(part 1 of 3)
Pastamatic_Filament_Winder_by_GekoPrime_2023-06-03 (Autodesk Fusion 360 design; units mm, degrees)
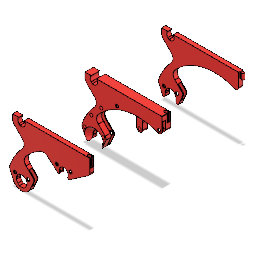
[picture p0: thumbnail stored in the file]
description: Spur Gear; Module: 2.0; Num Teeth: 20; Pressure Angle: 20.0; Backlash: 0.00 mm
description: Spur Gear; Module: 2.0; Num Teeth: 40; Pressure Angle: 20.0; Backlash: 0.00 mm
description: Spur Gear; Module: 2.0; Num Teeth: 10; Pressure Angle: 20.0; Backlash: 0.00 mm
description: Spur Gear; Module: 2.0; Num Teeth: 50; Pressure Angle: 20.0; Backlash: 0.00 mm
description: Spur Gear; Module: 2.0; Num Teeth: 30; Pressure Angle: 20.0; Backlash: 0.00 mm
parameter "bearing_od" = 22
parameter "bearing_id" = 8
parameter "bearing_z" = 7
parameter "spool_id_min" = 50
parameter "spool_id_max" = 60
parameter "spool_od_max" = 250
parameter "spool_z_max" = 120
parameter "ptfe_od" = 4
parameter "drive_span" = 6.65 (= "clearance_loose + 1 / 4 * 1 in")
parameter "overhang_angle" = 45
parameter "spool_z_min" = 50
parameter "spur_gear_z" = 7 (= "bearing_z")
parameter "spur_gear_diameter_medium" = 40
parameter "axle_od" = 26 (= "bearing_od + 2 * wall_thickness")
parameter "leadscrew_pitch" = 30 (= "spool_inner_z_bambu / leadscrew_turns")
parameter "leadscrew_tooth_height" = 3.3333 (= "leadscrew_od / 6")
parameter "clearance_loose" = 0.3
parameter "screw_od" = 22 (= "axle_od - 2 * wall_thickness")
parameter "screw_pitch" = 22 (= "screw_od")
parameter "screw_id" = 18 (= "screw_od - 2 * wall_thickness")
parameter "wall_thickness" = 2
parameter "washer_z" = 0.3 (= "clearance_loose")
parameter "leadscrew_angle" = 64.477 (= "atan(PI * leadscrew_od / leadscrew_pitch)")
parameter "washer_radial_thichness" = 1
parameter "internal_cavity_thickness" = 1
parameter "clearance_tight" = 0.01
parameter "buildplate_limit" = 240
parameter "spur_gear_diameter_small" = 20
parameter "stack_unit" = 11.6 (= "bearing_z + 2 * washer_z + 2 * wall_thickness")
parameter "fillet_radius" = 2 (= "wall_thickness")
parameter "spur_gear_diameter_large" = 100
parameter "ground_clearance" = 20
parameter "drive_depth" = 25.4
parameter "spool_id_bambu" = 54
parameter "spool_od_bambu" = 200
parameter "spool_inner_z_bambu" = 60
parameter "leadscrew_od" = 20
parameter "crossbar_od" = 20 (= "ground_clearance")
parameter "leadscrew_length" = 200
parameter "leadscrew_center_position" = 68.928
parameter "spur_gear_clearance" = 4
parameter "motor_mounting_circle" = 31
parameter "washer_taper" = -45
parameter "spool_interface_z_bambu" = 62
parameter "spool_od_min" = 200
sketch "Sketch1" plane through (0, 0, 0) normal (0, 0, 1) x axis (1, 0, 0)
  circle C1 centre (0, 0) radius 7.5492
extrude "Extrude1" new body sketch "Sketch1" along normal blind 7 bodies "spur_gear_10t_7mm"
sketch "Sketch2" plane through (0, 0, 0) normal (0, 0, 1) x axis (1, 0, 0)
  curve K1 (11.9856, -0.5875) -> (9.2583, -1.6082)
  curve K2 (11.9856, 0.5875) -> (9.2583, 1.6082)
  line L1 (9.2583, -1.6082) -> (7.428, -1.292)
  line L2 (9.2583, 1.6082) -> (7.428, 1.292)
  line L3 (7.428, 1.292) -> (7.428, -1.292)
  arc A1 centre (0, 0) radius 12 clockwise from (11.9856, 0.5875) to (11.9856, -0.5875)
extrude "Extrude2" add sketch "Sketch2" along normal blind 7
fillet "Fillet1" radius 1
circular_pattern "C-Pattern1" countU 10 TotalAngle 360
sketch "Sketch3" plane through (0, 0, 0) normal (0, 0, 1) x axis (1, 0, 0)
  circle C1 centre (0, 0) radius 10
sketch "Sketch1" plane through (0, 0, 0) normal (0, 0, 1) x axis (1, 0, 0)
  circle C1 centre (0, 0) radius 17.5492
  circle C2 centre (0, 0) radius 11
extrude "Extrude1" new body sketch "Sketch1" along normal blind 7 bodies "idler"
sketch "Sketch2" plane through (0, 0, 0) normal (0, 0, 1) x axis (1, 0, 0)
  curve K1 (21.989, -0.6948) -> (18.7119, -1.7536)
  curve K2 (21.989, 0.6948) -> (18.7119, 1.7536)
  line L1 (18.7119, -1.7536) -> (17.4627, -1.6375)
  line L2 (18.7119, 1.7536) -> (17.4627, 1.6375)
  line L3 (17.4627, 1.6375) -> (17.4627, -1.6375)
  arc A1 centre (0, 0) radius 22 clockwise from (21.989, 0.6948) to (21.989, -0.6948)
extrude "Extrude2" add sketch "Sketch2" along normal blind 7
fillet "Fillet1" radius 1
circular_pattern "C-Pattern1" countU 20 TotalAngle 360
sketch "Sketch3" plane through (0, 0, 0) normal (0, 0, 1) x axis (1, 0, 0)
  circle C1 centre (0, 0) radius 20
sketch "Sketch4" plane through (0, 0, 0) normal (1, 0, 0) x axis (0, 0, -1)
  line L1 (0, -22) -> (0, -21.989)
  line L2 (-7, -22) -> (-7, -21.989)
  line L3 (0, 21.989) -> (0, 22)
  line L4 (-7, 21.989) -> (-7, 22)
  line L5 (-7, -22) -> (0, -22)
  line L6 (-7, 22) -> (-7, -21.989)
  line L7 (0, -21.989) -> (0, 21.989)
  line L8 (-7, 19.652) -> (-4.663, 21.989)
  line L9 (0, 19.652) -> (-2.326, 22)
  line L10 (0, 0) -> (-7, 0.0055)
  line L11 (-3.5, 22) -> (-3.5, 19.652)
  line L12 (0, 19.652) -> (-3.5, 19.652)
  line L13 (-7, 19.652) -> (-3.5, 19.652)
  line L14 (-2.326, 22) -> (-4.663, 21.989)
  line L15 (0, 22) -> (-2.326, 22)
  line L16 (-7, 21.989) -> (-4.663, 21.989)
  point P4 (-7, -21.989)
  point P10 (-7, -21.989)
  point P9 (-7, 22)
  point P11 (-7, 22)
  point P6 (0, 21.989)
  point P12 (0, 21.989)
  point P2 (0, -21.989)
  point P13 (0, -21.989)
  point P15 (-7, 19.652)
  point P17 (0, 19.652)
  point P18 (-7, 0.0055)
  point P1 (0, 0)
  point P19 (0, 0)
  point P8 (0, 22)
  point P22 (0, 22)
  point P7 (-7, 21.989)
  point P23 (-7, 21.989)
  coincident P4 P10
  coincident P9 P11
  coincident P6 P12
  coincident P2 P13
  coincident L6 P15
  coincident L7 P17
  midpoint L6 P18
  coincident P1 P19
  equal L8 L9
  perpendicular L7 L12
  perpendicular L6 L13
  perpendicular L11 L12
  coincident P8 P22
  coincident P7 P23
  perpendicular L7 L15
  perpendicular L6 L16
  equal L12 L13
  equal L14 L16
  dimension "d1268" angle L6 L8 = 45
revolve "Revolve1" sketch "Sketch4" AlongAngle 360
chamfer "Chamfer1" distance 1
sketch "Sketch1" plane through (0, 0, 0) normal (0, 0, 1) x axis (1, 0, 0)
  circle C1 centre (0, 0) radius 37.5492
  circle C2 centre (0, 0) radius 11
extrude "Extrude1" new body sketch "Sketch1" along normal blind 7 bodies "spur_gear_40t_7mm"
sketch "Sketch2" plane through (0, 0, 0) normal (0, 0, 1) x axis (1, 0, 0)
  curve K1 (41.9931, -0.7606) -> (37.5326, -2.0353)
  curve K2 (41.9931, 0.7606) -> (37.5326, 2.0353)
  line L1 (37.5326, -2.0353) -> (37.4841, -2.0332)
  line L2 (37.5326, 2.0353) -> (37.4841, 2.0332)
  line L3 (37.4841, 2.0332) -> (37.4841, -2.0332)
  arc A1 centre (0, 0) radius 42 clockwise from (41.9931, 0.7606) to (41.9931, -0.7606)
extrude "Extrude2" add sketch "Sketch2" along normal blind 7
fillet "Fillet1" radius 1
circular_pattern "C-Pattern1" countU 40 TotalAngle 360
sketch "Sketch3" plane through (0, 0, 0) normal (0, 0, 1) x axis (1, 0, 0)
  circle C1 centre (0, 0) radius 40
sketch "Sketch1" plane through (0, 0, 0) normal (0, 0, 1) x axis (1, 0, 0)
  circle C1 centre (0, 0) radius 47.5492
extrude "Extrude1" new body sketch "Sketch1" along normal blind 7 bodies "spur_gear_50t_7mm"
sketch "Sketch2" plane through (0, 0, 0) normal (0, 0, 1) x axis (1, 0, 0)
  curve K1 (51.9942, -0.7754) -> (46.9342, -2.1756)
  curve K2 (51.9942, 0.7754) -> (46.9342, 2.1756)
  line L1 (46.9342, -2.1756) -> (46.9342, 2.1756)
  arc A1 centre (0, 0) radius 52 clockwise from (51.9942, 0.7754) to (51.9942, -0.7754)
extrude "Extrude2" add sketch "Sketch2" along normal blind 7
fillet "Fillet1" radius 1
circular_pattern "C-Pattern1" countU 50 TotalAngle 360
sketch "Sketch3" plane through (0, 0, 0) normal (0, 0, 1) x axis (1, 0, 0)
  circle C1 centre (0, 0) radius 50
sketch "Sketch5" plane through (0, 0, 0) normal (1, 0, 0) x axis (0, 0, -1)
  line L1 (-7, 51.9403) -> (0, 51.9403)
  line L2 (0, 49.607) -> (-3.5, 53.107)
  line L3 (0, 51.9403) -> (0, 49.607)
  line L4 (-7, 49.607) -> (-7, 51.9403)
  line L5 (-3.5, 53.107) -> (-7, 49.607)
  line L6 (-7, 53.107) -> (-7, 51.9403)
  line L7 (0, 53.107) -> (-7, 53.107)
  line L8 (0, 51.9403) -> (0, 53.107)
  point P2 (0, 51.9403)
  point P6 (0, 51.9403)
  point P3 (-7, 51.9403)
  point P7 (-7, 51.9403)
  point P10 (-7, 51.9403)
  point P13 (0, 51.9403)
  point P14 (-4.6667, 51.9403)
  point P15 (-2.3333, 51.9403)
  point P9 (-3.5, 53.107)
  point P4 (-3.5, 53.107)
  coincident P2 P6
  coincident P3 P7
  perpendicular L1 L4
  perpendicular L1 L3
  equal L2 L5
  equal L3 L4
  coincident P3 P10
  perpendicular L1 L6
  coincident P2 P13
  perpendicular L1 L8
  coincident L5 P14
  coincident L1 P14
  coincident L1 P15
  coincident L2 P15
  perpendicular L6 L7
  coincident P9 L7
  coincident P4 L7
  coincident P4 P9
  dimension "d1416" angle L4 L5 = 45
  dimension "d1419" distance P14 P15 = 2.3333 (= "bearing_z / 3")
revolve "Revolve1" sketch "Sketch5" AlongAngle 360
sketch "Sketch1" plane through (0, 0, 0) normal (0, 0, 1) x axis (1, 0, 0)
  line L1 (1.6583, -2.5) -> (-1.6583, -2.5)
  line L2 (4, 3) -> (-5, 3)
  circle C1 centre (0, 0) radius 7.5492
  circle C2 centre (0, 0) radius 3
  point P4 (-1.6583, -2.5)
  point P5 (1.6583, -2.5)
  concentric C1 C2
  coincident C2 P4
  coincident C2 P5
  horizontal L1
  horizontal L2
  tangent C2 L2
  dimension "d1565" distance L1 L2 = 5.5
  dimension "d1566" diameter C2 = 6
extrude "Extrude1" new body sketch "Sketch1" profile of C1 C2 L1 along normal blind 14 named "d988_1" bodies "spur_gear_10t_14mm_6mmD"
sketch "Sketch2" plane through (0, 0, 0) normal (0, 0, 1) x axis (1, 0, 0)
  curve K1 (11.9856, -0.5875) -> (9.2583, -1.6082)
  curve K2 (11.9856, 0.5875) -> (9.2583, 1.6082)
  line L1 (9.2583, -1.6082) -> (7.428, -1.292)
  line L2 (9.2583, 1.6082) -> (7.428, 1.292)
  line L3 (7.428, 1.292) -> (7.428, -1.292)
  arc A1 centre (0, 0) radius 12 clockwise from (11.9856, 0.5875) to (11.9856, -0.5875)
extrude "Extrude2" add sketch "Sketch2" along normal blind 14 named "d990_1"
fillet "Fillet1" radius 1 named "d993_1"
circular_pattern "C-Pattern1" countU 10 named "d994_1" TotalAngle 360 named "d995_1"
sketch "Sketch3" plane through (0, 0, 0) normal (0, 0, 1) x axis (1, 0, 0)
  circle C1 centre (0, 0) radius 10
sketch "Sketch4" plane through (0, 0, 0) normal (0, 1, 0) x axis (1, 0, 0)
  line L1 (0, 0) -> (0, -14)
  line L2 (9.6667, 0) -> (0, 0)
  line L3 (12, -2.3333) -> (9.6667, 0)
  line L4 (12, -11.6667) -> (12, -2.3333)
  line L5 (9.6667, -14) -> (12, -11.6667)
  line L6 (0, -14) -> (9.6667, -14)
  line L7 (0, -7) -> (12, -7)
  point P1 (0, 0)
  point P3 (0, 0)
  point P8 (12, -7)
  point P9 (0, -7)
  point P2 (0, -14)
  point P5 (12, -2.3333)
  point P6 (12, -11.6667)
  coincident P1 P3
  vertical L1
  perpendicular L1 L2
  perpendicular L2 L4
  perpendicular L1 L6
  equal L3 L5
  midpoint L4 P8
  midpoint L1 P9
  perpendicular L4 L7
  dimension "d1567" distance P2 P3 = 14
  dimension "d1568" distance L1 L4 = 12 (= "spur_gear_diameter_small / 2 + spur_gear_clearance / 2")
  dimension "d1569" angle L5 L6 = 45
  dimension "d1570" distance P5 P6 = 9.3333 (= "7 mm + ( 7 / 3 ) * 1 mm")
revolve "Revolve1" sketch "Sketch4" AlongAngle 360
sketch "Sketch1" plane through (0, 0, 0) normal (0, 0, 1) x axis (1, 0, 0)
  circle C1 centre (0, 0) radius 27.5492
extrude "Extrude1" new body sketch "Sketch1" along normal blind 7 bodies "spur_gear_30t_7mm"
sketch "Sketch2" plane through (0, 0, 0) normal (0, 0, 1) x axis (1, 0, 0)
  curve K1 (31.9915, -0.7373) -> (28.127, -1.8948)
  curve K2 (31.9915, 0.7373) -> (28.127, 1.8948)
  line L1 (28.127, -1.8948) -> (27.4769, -1.8517)
  line L2 (28.127, 1.8948) -> (27.4769, 1.8517)
  line L3 (27.4769, 1.8517) -> (27.4769, -1.8517)
  arc A1 centre (0, 0) radius 32 clockwise from (31.9915, 0.7373) to (31.9915, -0.7373)
extrude "Extrude2" add sketch "Sketch2" along normal blind 7
fillet "Fillet1" radius 1
circular_pattern "C-Pattern1" countU 30 TotalAngle 360
sketch "Sketch3" plane through (0, 0, 0) normal (0, 0, 1) x axis (1, 0, 0)
  circle C1 centre (0, 0) radius 30
copy_paste_bodies "CopyPasteBodies3"
copy_paste_bodies "CopyPasteBodies2"
align "Align1"
move "Move1" TranslateX 0 TranslateY 0 TranslateZ -4 (= "-2 * wall_thickness")
sketch "Sketch1" plane through (0, 0, 7) normal (0, 0, 1) x axis (1, 0, 0)
  curve K1 (27.4076, 2.7893) -> (28.3353, 1.8928)
  curve K2 (31.9915, 0.7373) -> (28.3353, 1.8928)
  curve K3 (28.3353, -1.8928) -> (31.9915, -0.7373)
  curve K4 (28.3353, -1.8928) -> (27.4076, -2.7893)
  curve K5 (27.3886, -2.97) -> (28.1096, -4.0398)
  curve K6 (31.4457, -5.9302) -> (28.1096, -4.0398)
  curve K7 (27.3226, -7.7427) -> (31.1391, -7.3726)
  curve K8 (27.3226, -7.7427) -> (26.2288, -8.4267)
  curve K9 (26.1726, -8.5996) -> (26.6554, -9.7959)
  curve K10 (29.5256, -12.3385) -> (26.6554, -9.7959)
  curve K11 (25.1157, -13.2541) -> (28.9258, -13.6857)
  curve K12 (25.1157, -13.2541) -> (23.9036, -13.6958)
  curve K13 (23.8127, -13.8532) -> (24.0363, -15.1238)
  curve K14 (26.3151, -18.2076) -> (24.0363, -15.1238)
  curve K15 (21.8112, -18.1864) -> (25.4483, -19.4007)
  curve K16 (21.8112, -18.1864) -> (20.5337, -18.3664)
  curve K17 (20.4121, -18.5015) -> (20.3666, -19.7907)
  curve K18 (21.9544, -23.2809) -> (20.3666, -19.7907)
  curve K19 (17.5534, -22.3237) -> (20.8585, -24.2677)
  curve K20 (17.5534, -22.3237) -> (16.2665, -22.2342)
  curve K21 (16.1194, -22.3411) -> (15.8068, -23.5927)
  curve K22 (16.6343, -27.3368) -> (15.8068, -23.5927)
  curve K23 (12.5284, -25.4855) -> (15.3572, -28.0741)
  curve K24 (12.5284, -25.4855) -> (11.2882, -25.1303)
  curve K25 (11.1222, -25.2043) -> (10.5562, -26.3636)
  curve K26 (10.5872, -30.1979) -> (10.5562, -26.3636)
  curve K27 (6.9559, -27.5334) -> (9.1847, -30.6536)
  curve K28 (6.9559, -27.5334) -> (5.8167, -26.9281)
  curve K29 (5.6389, -26.9659) -> (4.8443, -27.9822)
  curve K30 (4.0773, -31.7392) -> (4.8443, -27.9822)
  curve K31 (1.0794, -28.3779) -> (2.6107, -31.8933)
  curve K32 (1.0794, -28.3779) -> (0.0909, -27.5491)
  curve K33 (-0.0909, -27.5491) -> (-1.0794, -28.3779)
  curve K34 (-2.6107, -31.8933) -> (-1.0794, -28.3779)
  curve K35 (-4.8443, -27.9822) -> (-4.0773, -31.7392)
  curve K36 (-4.8443, -27.9822) -> (-5.6389, -26.9659)
  curve K37 (-5.8167, -26.9281) -> (-6.9559, -27.5334)
  curve K38 (-9.1847, -30.6536) -> (-6.9559, -27.5334)
  curve K39 (-10.5562, -26.3636) -> (-10.5872, -30.1979)
  curve K40 (-10.5562, -26.3636) -> (-11.1222, -25.2043)
  curve K41 (-11.2882, -25.1303) -> (-12.5284, -25.4855)
  curve K42 (-15.3572, -28.0741) -> (-12.5284, -25.4855)
  curve K43 (-15.8068, -23.5927) -> (-16.6343, -27.3368)
  curve K44 (-15.8068, -23.5927) -> (-16.1194, -22.3411)
  curve K45 (-16.2665, -22.2342) -> (-17.5534, -22.3237)
  curve K46 (-20.8585, -24.2677) -> (-17.5534, -22.3237)
  curve K47 (-20.3666, -19.7907) -> (-21.9544, -23.2809)
  curve K48 (-20.3666, -19.7907) -> (-20.4121, -18.5015)
  curve K49 (-20.5337, -18.3664) -> (-21.8112, -18.1864)
  curve K50 (-25.4483, -19.4007) -> (-21.8112, -18.1864)
  curve K51 (-24.0363, -15.1238) -> (-26.3151, -18.2076)
  curve K52 (-24.0363, -15.1238) -> (-23.8127, -13.8532)
  curve K53 (-23.9036, -13.6958) -> (-25.1157, -13.2541)
  curve K54 (-28.9258, -13.6857) -> (-25.1157, -13.2541)
  curve K55 (-26.6554, -9.7959) -> (-29.5256, -12.3385)
  curve K56 (-26.6554, -9.7959) -> (-26.1726, -8.5996)
  curve K57 (-26.2288, -8.4267) -> (-27.3226, -7.7427)
  curve K58 (-31.1391, -7.3726) -> (-27.3226, -7.7427)
  curve K59 (-28.1096, -4.0398) -> (-31.4457, -5.9302)
  curve K60 (-28.1096, -4.0398) -> (-27.3886, -2.97)
  curve K61 (-27.4076, -2.7893) -> (-28.3353, -1.8928)
  curve K62 (-31.9915, -0.7373) -> (-28.3353, -1.8928)
  curve K63 (-28.3353, 1.8928) -> (-31.9915, 0.7373)
  curve K64 (-28.3353, 1.8928) -> (-27.4076, 2.7893)
  curve K65 (-27.3886, 2.97) -> (-28.1096, 4.0398)
  curve K66 (-31.4457, 5.9302) -> (-28.1096, 4.0398)
  curve K67 (-27.3226, 7.7427) -> (-31.1391, 7.3726)
  curve K68 (-27.3226, 7.7427) -> (-26.2288, 8.4267)
  curve K69 (-26.1726, 8.5996) -> (-26.6554, 9.7959)
  curve K70 (-29.5256, 12.3385) -> (-26.6554, 9.7959)
  curve K71 (-25.1157, 13.2541) -> (-28.9258, 13.6857)
  curve K72 (-25.1157, 13.2541) -> (-23.9036, 13.6958)
  curve K73 (-23.8127, 13.8532) -> (-24.0363, 15.1238)
  curve K74 (-26.3151, 18.2076) -> (-24.0363, 15.1238)
  curve K75 (-21.8112, 18.1864) -> (-25.4483, 19.4007)
  curve K76 (-21.8112, 18.1864) -> (-20.5337, 18.3664)
  curve K77 (-20.4121, 18.5015) -> (-20.3666, 19.7907)
  curve K78 (-21.9544, 23.2809) -> (-20.3666, 19.7907)
  curve K79 (-17.5534, 22.3237) -> (-20.8585, 24.2677)
  curve K80 (-17.5534, 22.3237) -> (-16.2665, 22.2342)
  curve K81 (-16.1194, 22.3411) -> (-15.8068, 23.5927)
  curve K82 (-16.6343, 27.3368) -> (-15.8068, 23.5927)
  curve K83 (-12.5284, 25.4855) -> (-15.3572, 28.0741)
  curve K84 (-12.5284, 25.4855) -> (-11.2882, 25.1303)
  curve K85 (-11.1222, 25.2043) -> (-10.5562, 26.3636)
  curve K86 (-10.5872, 30.1979) -> (-10.5562, 26.3636)
  curve K87 (-6.9559, 27.5334) -> (-9.1847, 30.6536)
  curve K88 (-6.9559, 27.5334) -> (-5.8167, 26.9281)
  curve K89 (-5.6389, 26.9659) -> (-4.8443, 27.9822)
  curve K90 (-4.0773, 31.7392) -> (-4.8443, 27.9822)
  curve K91 (-1.0794, 28.3779) -> (-2.6107, 31.8933)
  curve K92 (-1.0794, 28.3779) -> (-0.0909, 27.5491)
  curve K93 (0.0909, 27.5491) -> (1.0794, 28.3779)
  curve K94 (2.6107, 31.8933) -> (1.0794, 28.3779)
  curve K95 (4.8443, 27.9822) -> (4.0773, 31.7392)
  curve K96 (4.8443, 27.9822) -> (5.6389, 26.9659)
  curve K97 (5.8167, 26.9281) -> (6.9559, 27.5334)
  curve K98 (9.1847, 30.6536) -> (6.9559, 27.5334)
  curve K99 (10.5562, 26.3636) -> (10.5872, 30.1979)
  curve K100 (10.5562, 26.3636) -> (11.1222, 25.2043)
  curve K101 (11.2882, 25.1303) -> (12.5284, 25.4855)
  curve K102 (15.3572, 28.0741) -> (12.5284, 25.4855)
  curve K103 (15.8068, 23.5927) -> (16.6343, 27.3368)
  curve K104 (15.8068, 23.5927) -> (16.1194, 22.3411)
  curve K105 (16.2665, 22.2342) -> (17.5534, 22.3237)
  curve K106 (20.8585, 24.2677) -> (17.5534, 22.3237)
  curve K107 (20.3666, 19.7907) -> (21.9544, 23.2809)
  curve K108 (20.3666, 19.7907) -> (20.4121, 18.5015)
  curve K109 (20.5337, 18.3664) -> (21.8112, 18.1864)
  curve K110 (25.4483, 19.4007) -> (21.8112, 18.1864)
  curve K111 (24.0363, 15.1238) -> (26.3151, 18.2076)
  curve K112 (24.0363, 15.1238) -> (23.8127, 13.8532)
  curve K113 (23.9036, 13.6958) -> (25.1157, 13.2541)
  curve K114 (28.9258, 13.6857) -> (25.1157, 13.2541)
  curve K115 (26.6554, 9.7959) -> (29.5256, 12.3385)
  curve K116 (26.6554, 9.7959) -> (26.1726, 8.5996)
  curve K117 (26.2288, 8.4267) -> (27.3226, 7.7427)
  curve K118 (31.1391, 7.3726) -> (27.3226, 7.7427)
  curve K119 (28.1096, 4.0398) -> (31.4457, 5.9302)
  curve K120 (28.1096, 4.0398) -> (27.3886, 2.97)
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  point P1 (0, 0)
  point P2 (0, 0)
  coincident P1 P2
  dimension "d1501" distance = 2 (= "wall_thickness")
  dimension "d1748" diameter = 50.3377 (= "spur_gear_conversion_diameter - 2 * spur_gear_clearance - 2 * wall_thickness")
  dimension "d1749" distance = 2 (= "wall_thickness")
  dimension "d1750" distance = 2 (= "wall_thickness")
  dimension "d1751" angle = 36 (= "( 360 / 10 ) * 1 deg")
extrude "Extrude7" cut sketch "Sketch1" no distance stored
fillet "Fillet2" radius 2 (= "wall_thickness")
chamfer "Chamfer3" distance 0.5 (= "wall_thickness / 4")
circular_pattern "C-Pattern3" countU 10 TotalAngle 360
loft "Loft2" sketch "Sketch1" bodies "spur_gear_30t_7mm"
extrude "Extrude5" cut sketch "Sketch1" no distance stored
sketch "Sketch2" plane through (0, 0, -4) normal (0, 0, -1) x axis (-1, 0, 0)
  line L1 (-4.3904, -8.3082) -> (-3.9672, -7.5055)
  curve K1 (-4.2625, -11.2175) -> (-4.3904, -8.3082)
  curve K2 (-3.145, -11.5805) -> (-1.3315, -9.3021)
  line L2 (-1.2021, -8.404) -> (-1.3315, -9.3021)
  line L3 (1.3315, -9.3021) -> (1.2021, -8.404)
  curve K3 (3.145, -11.5805) -> (1.3315, -9.3021)
  curve K4 (4.2625, -11.2175) -> (4.3904, -8.3082)
  line L4 (3.9672, -7.5055) -> (4.3904, -8.3082)
  line L5 (6.5449, -6.7429) -> (5.9123, -6.0924)
  curve K5 (9.3513, -7.5202) -> (6.5449, -6.7429)
  curve K6 (10.0419, -6.5697) -> (8.4354, -4.1409)
  line L6 (7.6212, -3.7403) -> (8.4354, -4.1409)
  line L7 (9.2583, -1.6082) -> (8.3641, -1.4537)
  curve K7 (11.9856, -0.5875) -> (9.2583, -1.6082)
  curve K8 (11.9856, 0.5875) -> (9.2583, 1.6082)
  line L8 (8.3641, 1.4537) -> (9.2583, 1.6082)
  line L9 (8.4354, 4.1409) -> (7.6212, 3.7403)
  curve K9 (10.0419, 6.5697) -> (8.4354, 4.1409)
  curve K10 (9.3513, 7.5202) -> (6.5449, 6.7429)
  line L10 (5.9123, 6.0924) -> (6.5449, 6.7429)
  line L11 (4.3904, 8.3082) -> (3.9672, 7.5055)
  curve K11 (4.2625, 11.2175) -> (4.3904, 8.3082)
  curve K12 (3.145, 11.5805) -> (1.3315, 9.3021)
  line L12 (1.2021, 8.404) -> (1.3315, 9.3021)
  line L13 (-1.3315, 9.3021) -> (-1.2021, 8.404)
  curve K13 (-3.145, 11.5805) -> (-1.3315, 9.3021)
  curve K14 (-4.2625, 11.2175) -> (-4.3904, 8.3082)
  line L14 (-3.9672, 7.5055) -> (-4.3904, 8.3082)
  line L15 (-6.5449, 6.7429) -> (-5.9123, 6.0924)
  curve K15 (-9.3513, 7.5202) -> (-6.5449, 6.7429)
  curve K16 (-10.0419, 6.5697) -> (-8.4354, 4.1409)
  line L16 (-7.6212, 3.7403) -> (-8.4354, 4.1409)
  line L17 (-9.2583, 1.6082) -> (-8.3641, 1.4537)
  curve K17 (-11.9856, 0.5875) -> (-9.2583, 1.6082)
  curve K18 (-11.9856, -0.5875) -> (-9.2583, -1.6082)
  line L18 (-8.3641, -1.4537) -> (-9.2583, -1.6082)
  line L19 (-8.4354, -4.1409) -> (-7.6212, -3.7403)
  curve K19 (-10.0419, -6.5697) -> (-8.4354, -4.1409)
  curve K20 (-9.3513, -7.5202) -> (-6.5449, -6.7429)
  line L20 (-5.9123, -6.0924) -> (-6.5449, -6.7429)
  arc A1 centre (-4.8518, -7.0391) radius 1 clockwise from (-4.2842, -6.2158) to (-3.9672, -7.5055)
  arc A2 centre (0, 0) radius 12 clockwise from (-3.145, -11.5805) to (-4.2625, -11.2175)
  arc A3 centre (-0.2123, -8.5466) radius 1 clockwise from (-1.2021, -8.404) to (-0.1875, -7.5469)
  arc A4 centre (0, 0) radius 7.5492 clockwise from (0.1875, -7.5469) to (-0.1875, -7.5469)
  arc A5 centre (0.2123, -8.5466) radius 1 clockwise from (0.1875, -7.5469) to (1.2021, -8.404)
  arc A6 centre (0, 0) radius 12 clockwise from (4.2625, -11.2175) to (3.145, -11.5805)
  arc A7 centre (4.8518, -7.0391) radius 1 clockwise from (3.9672, -7.5055) to (4.2842, -6.2158)
  arc A8 centre (0, 0) radius 7.5492 clockwise from (4.5876, -5.9953) to (4.2842, -6.2158)
  arc A9 centre (5.1953, -6.7895) radius 1 clockwise from (4.5876, -5.9953) to (5.9123, -6.0924)
  arc A10 centre (0, 0) radius 12 clockwise from (10.0419, -6.5697) to (9.3513, -7.5202)
  arc A11 centre (8.0626, -2.843) radius 1 clockwise from (7.6212, -3.7403) to (7.1196, -2.5104)
  arc A12 centre (0, 0) radius 7.5492 clockwise from (7.2354, -2.1538) to (7.1196, -2.5104)
  arc A13 centre (8.1939, -2.4391) radius 1 clockwise from (7.2354, -2.1538) to (8.3641, -1.4537)
  arc A14 centre (0, 0) radius 12 clockwise from (11.9856, 0.5875) to (11.9856, -0.5875)
  arc A15 centre (8.1939, 2.4391) radius 1 clockwise from (8.3641, 1.4537) to (7.2354, 2.1538)
  arc A16 centre (0, 0) radius 7.5492 clockwise from (7.1196, 2.5104) to (7.2354, 2.1538)
  arc A17 centre (8.0626, 2.843) radius 1 clockwise from (7.1196, 2.5104) to (7.6212, 3.7403)
  arc A18 centre (0, 0) radius 12 clockwise from (9.3513, 7.5202) to (10.0419, 6.5697)
  arc A19 centre (5.1953, 6.7895) radius 1 clockwise from (5.9123, 6.0924) to (4.5876, 5.9953)
  arc A20 centre (0, 0) radius 7.5492 clockwise from (4.2842, 6.2158) to (4.5876, 5.9953)
  arc A21 centre (4.8518, 7.0391) radius 1 clockwise from (4.2842, 6.2158) to (3.9672, 7.5055)
  arc A22 centre (0, 0) radius 12 clockwise from (3.145, 11.5805) to (4.2625, 11.2175)
  arc A23 centre (0.2123, 8.5466) radius 1 clockwise from (1.2021, 8.404) to (0.1875, 7.5469)
  arc A24 centre (0, 0) radius 7.5492 clockwise from (-0.1875, 7.5469) to (0.1875, 7.5469)
  arc A25 centre (-0.2123, 8.5466) radius 1 clockwise from (-0.1875, 7.5469) to (-1.2021, 8.404)
  arc A26 centre (0, 0) radius 12 clockwise from (-4.2625, 11.2175) to (-3.145, 11.5805)
  arc A27 centre (-4.8518, 7.0391) radius 1 clockwise from (-3.9672, 7.5055) to (-4.2842, 6.2158)
  arc A28 centre (0, 0) radius 7.5492 clockwise from (-4.5876, 5.9953) to (-4.2842, 6.2158)
  arc A29 centre (-5.1953, 6.7895) radius 1 clockwise from (-4.5876, 5.9953) to (-5.9123, 6.0924)
  arc A30 centre (0, 0) radius 12 clockwise from (-10.0419, 6.5697) to (-9.3513, 7.5202)
  arc A31 centre (-8.0626, 2.843) radius 1 clockwise from (-7.6212, 3.7403) to (-7.1196, 2.5104)
  arc A32 centre (0, 0) radius 7.5492 clockwise from (-7.2354, 2.1538) to (-7.1196, 2.5104)
  arc A33 centre (-8.1939, 2.4391) radius 1 clockwise from (-7.2354, 2.1538) to (-8.3641, 1.4537)
  arc A34 centre (0, 0) radius 12 clockwise from (-11.9856, -0.5875) to (-11.9856, 0.5875)
  arc A35 centre (-8.1939, -2.4391) radius 1 clockwise from (-8.3641, -1.4537) to (-7.2354, -2.1538)
  arc A36 centre (0, 0) radius 7.5492 clockwise from (-7.1196, -2.5104) to (-7.2354, -2.1538)
  arc A37 centre (-8.0626, -2.843) radius 1 clockwise from (-7.1196, -2.5104) to (-7.6212, -3.7403)
  arc A38 centre (0, 0) radius 12 clockwise from (-9.3513, -7.5202) to (-10.0419, -6.5697)
  arc A39 centre (-5.1953, -6.7895) radius 1 clockwise from (-5.9123, -6.0924) to (-4.5876, -5.9953)
  arc A40 centre (0, 0) radius 7.5492 clockwise from (-4.2842, -6.2158) to (-4.5876, -5.9953)
  circle C1 centre (0, 0) radius 4.15
  concentric A2 C1
  dimension "d1622" diameter C1 = 8.3 (= "bearing_id + clearance_loose")
loft "Loft3" sketch "Sketch2" + "Sketch1" Start TakeOff Angle 0
sketch "Sketch3" plane through (0, 0, 0) normal (0, 1, 0) x axis (1, 0, 0)
  line L1 (0, -14) -> (-32, -14)
  line L2 (0, 4) -> (0, -14)
  line L3 (-12, 4) -> (0, 4)
  line L4 (-12, -3) -> (-12, 4)
  line L5 (-32, -7) -> (-12, -3)
  line L6 (-32, -14) -> (-32, -7)
  line L7 (-29.6667, -14) -> (-32, -11.6667)
  line L8 (-12, -7) -> (-32, -7)
  line L9 (-12, -3) -> (-12, -7)
  line L10 (-29.6667, -7) -> (-32, -9.3333)
  line L11 (-9.6667, 4) -> (-12, 1.6667)
  point P7 (-32, -7)
  point P8 (0, -7)
  point P9 (-32, -11.6667)
  point P10 (-29.6667, -14)
  point P12 (-32, -9.3333)
  point P13 (-29.6667, -7)
  point P14 (-12, 1.6667)
  point P15 (-9.6667, 4)
  point P5 (-12, 4)
  point P6 (-12, -3)
  point P2 (-32, -14)
  point P4 (0, 4)
  point P3 (0, -14)
  horizontal L1
  perpendicular L1 L2
  perpendicular L2 L3
  perpendicular L3 L4
  perpendicular L1 L6
  horizontal P7 P8
  coincident L2 P8
  coincident L6 P9
  coincident L1 P10
  perpendicular L6 L8
  perpendicular L8 L9
  coincident L6 P12
  coincident L8 P13
  coincident L4 P14
  coincident L3 P15
  equal L7 L10
  equal L10 L11
  perpendicular L7 L10
  parallel L10 L11
  dimension "d1626" distance P5 P6 = 7 (= "bearing_z")
  dimension "d1627" distance P2 P7 = 7 (= "bearing_z")
  dimension "d1628" distance P6 P7 = 4 (= "2 * wall_thickness")
  dimension "d1629" distance P4 P5 = 12 (= "spur_gear_diameter_small / 2 + spur_gear_clearance / 2")
  dimension "d1630" distance P2 P3 = 32 (= "( 60 / 2 ) * 1 mm + spur_gear_clearance / 2")
  dimension "d1631" angle L1 L7 = 45
  dimension "d1632" distance P9 P12 = 2.3333 (= "bearing_z / 3")
revolve "Revolve1" sketch "Sketch3" AlongAngle 360
chamfer "Chamfer2" distance 0.5 (= "wall_thickness / 4")
sketch "Sketch1" plane through (0, 0, 0) normal (0, 0, 1) x axis (1, 0, 0)
  line L1 (0, 5) -> (0, -5)
  line L2 (24.6, -10.3) -> (24.6, 10.3)
  line L3 (49.22, -10.3) -> (24.6, -10.3)
  line L4 (49.22, 10.3) -> (49.22, -10.3)
  line L5 (24.6, 10.3) -> (49.22, 10.3)
  line L6 (49.21, -10.29) -> (24.61, -10.29)
  line L7 (49.21, 10.29) -> (49.21, -10.29)
  line L8 (24.61, 10.29) -> (49.21, 10.29)
  line L9 (24.61, -10.29) -> (24.61, 10.29)
  line L10 (0, -5) -> (24.6, -5)
  line L11 (12.3, 5) -> (12.3, -5)
  line L12 (24.6, 5) -> (0, 5)
  line L13 (24.6, 0) -> (0, 0)
  line L14 (51.21, 12.3) -> (0, 12.3)
  line L15 (51.21, -12.3) -> (51.21, 12.3)
  line L16 (0, -12.3) -> (51.21, -12.3)
  line L17 (66, -55) -> (66, 55)
  line L18 (66, 0) -> (51.21, 0)
  line L19 (-34.4247, 0) -> (0, 0)
  line L20 (-34.4247, 4) -> (-18.4247, 4)
  line L21 (-18.4247, -4) -> (-34.4247, -4)
  circle C1 centre (0, 0) radius 10
  circle C2 centre (0, 0) radius 10.3
  arc A1 centre (-34.4247, 0) radius 4 clockwise from (-34.4247, -4) to (-34.4247, 4)
  circle C3 centre (0, 0) radius 12.3
  arc A2 centre (-18.4247, 16.3) radius 12.3 clockwise from (-9.2124, 8.15) to (-18.4247, 4)
  arc A3 centre (-18.4247, -16.3) radius 12.3 clockwise from (-18.4247, -4) to (-9.2124, -8.15)
  arc A4 centre (62, 40) radius 4 clockwise from (58.7574, 42.3421) to (65.0379, 37.3978)
  arc A5 centre (62, -40) radius 4 clockwise from (65.0378, -37.3978) to (58.7574, -42.3421)
  arc A6 centre (0, -84.7809) radius 72.4809 clockwise from (0, -12.3) to (58.7574, -42.3421)
  arc A7 centre (0, 84.7809) radius 72.4809 clockwise from (58.7574, 42.3421) to (0, 12.3)
  arc A8 centre (108.6956, 0) radius 57.4856 clockwise from (65.0378, -37.3978) to (65.0379, 37.3978)
  point P1 (0, 0)
  point P3 (0, 0)
  point P6 (0, 0)
  point P7 (10.3, 0)
  point P20 (24.6, 0)
  point P21 (24.6, -5)
  point P22 (12.3, -5)
  point P24 (24.6, 5)
  point P23 (12.3, 5)
  point P19 (0, 0)
  point P25 (0, 0)
  point P26 (24.6, 0)
  point P27 (0, 12.3)
  point P30 (0, -12.3)
  point P33 (51.21, 0)
  point P34 (66, 0)
  point P35 (0, 0)
  point P16 (-34.4247, 0)
  point P36 (-34.4247, 0)
  point P39 (-9.2124, 8.15)
  point P41 (-9.2124, -8.15)
  point P55 (108.6956, 0)
  point P51 (0, -12.3)
  point P53 (0, 12.3)
  point P47 (58.7574, -42.3421)
  point P50 (58.7574, -42.3421)
  point P45 (58.7574, 42.3421)
  point P54 (58.7574, 42.3421)
  point P44 (65.0379, 37.3978)
  point P56 (65.0379, 37.3978)
  point P48 (65.0378, -37.3978)
  point P57 (65.0378, -37.3978)
  point P2 (0, 0)
  point P18 (-34.4247, -4)
  point P42 (-18.4247, -4)
  point P43 (62, 40)
  point P46 (62, -40)
  coincident P1 P3
  midpoint L1 P6
  coincident P1 P6
  coincident C2 P7
  perpendicular L2 L3
  perpendicular L2 L5
  concentric C2 C3
  vertical L1
  perpendicular L4 L5
  midpoint L2 P20
  coincident L2 P21
  perpendicular L2 L10
  midpoint L10 P22
  perpendicular L10 L11
  vertical L11
  coincident L2 P24
  perpendicular L9 L12
  midpoint P23 L12
  coincident P19 P25
  horizontal L13
  coincident P20 P26
  equal L6 L10
  tangent C3 L11
  tangent C2 L5
  coincident C3 P27
  horizontal L14
  perpendicular L14 L15
  tangent C3 L16
  perpendicular L15 L16
  tangent C3 L14
  coincident C3 P30
  vertical L17
  midpoint L15 P33
  midpoint L17 P34
  perpendicular L17 L18
  coincident P3 P35
  coincident P16 P36
  horizontal L19
  coincident C3 P39
  coincident C3 P41
  tangent A1 L20
  tangent A1 L21
  tangent A3 L21
  tangent A2 L20
  tangent C3 A2
  tangent C3 A3
  equal L20 L21
  equal A2 A3
  parallel L20 L21
  equal A1 A4
  equal A1 A5
  coincident L18 P55
  tangent L16 A6
  tangent L14 A7
  tangent L17 A4
  tangent L17 A5
  tangent L15 A8
  equal C3 A2
  coincident L16 P51
  coincident L14 P53
  coincident P27 P53
  coincident P30 P51
  equal A6 A7
  coincident P47 P50
  tangent A5 A6
  coincident P45 P54
  tangent A4 A7
  coincident P44 P56
  coincident P48 P57
  tangent A5 A8
  dimension "d747" diameter C1 = 20 (= "leadscrew_od")
  dimension "d749" distance C1 C2 = 0.3 (= "clearance_loose")
  dimension "d1302" distance C2 C3 = 2 (= "wall_thickness")
  dimension "d1313" distance L10 L12 = 10 (= "leadscrew_od / 2")
  dimension "d1538" distance L7 L15 = 2 (= "wall_thickness")
  dimension "d1545" distance P2 L17 = 66
  dimension "d1546" radius A1 = 4 (= "2 * wall_thickness")
  dimension "d1548" distance P18 P42 = 16 (= "ptfe_od * 4")
  dimension "d1706" distance P43 P46 = 80
extrude "Extrude2" new body sketch "Sketch1" profile of C2 L2 L3 L4 L5 A1 C3 L10 L12 L13 L14 L15 L16 A2 A3 L20 L21 A4 A5 A6 A7 A8 distance 20 (= "leadscrew_od") bodies "leadscrew_block"
sketch "tooth_hole" plane through (0, 0, 0) normal (1, 0, 0) x axis (0, 0, -1)
  line L1 (-7.2832, 0) -> (-3.6416, -3.6416)
  line L2 (-3.6416, 3.6416) -> (-7.2832, 0)
  line L3 (-10, -10.3) -> (-10, 10.3)
  line L4 (10, 10.3) -> (10, -10.3)
  line L5 (7.2832, 0) -> (3.6416, -3.6416)
  line L6 (-7.2832, 0) -> (7.2832, 0)
  line L7 (3.6416, 3.6416) -> (7.2832, 0)
  line L8 (-10, 10.3) -> (10, 10.3)
  line L9 (10, -10.3) -> (-10, -10.3)
  line L10 (-5.15, 2.1332) -> (-5.15, -2.1332)
  line L11 (5.15, 2.1332) -> (5.15, -2.1332)
  line L12 (-10, -10.3) -> (10, -10.3)
  line L13 (-10, 10.3) -> (-10, -10.3)
  line L14 (10, 10.3) -> (-10, 10.3)
  line L15 (10, -10.3) -> (10, 10.3)
  circle C1 centre (0, 0) radius 5.15
  circle C2 centre (0, 0) radius 5
  point P1 (0, 0)
  point P2 (0, 0)
  point P3 (-3.6416, -3.6416)
  point P5 (-3.6416, 3.6416)
  point P11 (3.6416, -3.6416)
  point P10 (0, 0)
  point P13 (3.6416, 3.6416)
  point P14 (-5.15, -2.1332)
  point P15 (-5.15, 2.1332)
  point P16 (5.15, -2.1332)
  point P17 (5.15, 2.1332)
  coincident P1 P2
  coincident C1 P3
  coincident C1 P5
  tangent C1 L1
  tangent C1 L2
  coincident C1 P11
  midpoint P10 L6
  horizontal L6
  coincident C1 P13
  tangent C1 L5
  tangent C1 L7
  coincident L1 P14
  coincident L2 P15
  vertical L10
  coincident L5 P16
  coincident L7 P17
  tangent C1 L10
  tangent C1 L11
  perpendicular L6 L11
  dimension "d790" distance C1 C2 = 0.15 (= "clearance_loose / 2")
  dimension "d845" angle L1 L6 = 45 (= "overhang_angle")
  dimension "d1420" diameter C2 = 10 (= "leadscrew_od / 2")
extrude "Extrude11" cut sketch "tooth_hole" profile of C1 L1 L2 L5 L7 L10 L11 to an object
sketch "Sketch44" plane through (0, -4, 0) normal (0, -1, 0) x axis (1, 0, 0)
  line L1 (-18.4247, -10) -> (-34.4247, 10)
  line L2 (-18.4247, 10) -> (-18.4247, -10)
  line L3 (-34.4247, 10) -> (-18.4247, 10)
  line L4 (-34.4247, -10) -> (-34.4247, 10)
  line L5 (-18.4247, -10) -> (-34.4247, -10)
  line L6 (-25.9247, 2.3284) -> (-26.9247, 2.3284)
  line L7 (-25.0105, 1.4142) -> (-25.9247, 2.3284)
  line L8 (-26.9247, 2.3284) -> (-27.8389, 1.4142)
  line L9 (-26.9247, -2.3284) -> (-27.8389, -1.4142)
  line L10 (-25.9247, -2.3284) -> (-26.9247, -2.3284)
  line L11 (-25.0105, -1.4142) -> (-25.9247, -2.3284)
  line L12 (-26.4247, -2.3284) -> (-26.4247, 2.3284)
  circle C1 centre (-26.4247, 0) radius 2
  point P2 (-26.4247, 0)
  point P3 (-34.4247, 10)
  point P7 (-34.4247, 10)
  point P4 (-18.4247, -10)
  point P5 (-18.4247, -10)
  point P11 (-25.0105, 1.4142)
  point P12 (-27.8389, 1.4142)
  point P13 (-27.8389, -1.4142)
  point P16 (-25.0105, -1.4142)
  point P17 (-26.4247, 2.3284)
  point P18 (-26.4247, -2.3284)
  point P9 (-26.9247, 2.3284)
  point P10 (-25.9247, 2.3284)
  midpoint P2 L1
  coincident P3 P7
  coincident P4 P5
  horizontal L6
  coincident C1 P11
  coincident C1 P12
  coincident C1 P13
  parallel L6 L10
  coincident C1 P16
  parallel L8 L11
  tangent C1 L8
  tangent C1 L9
  tangent C1 L11
  tangent C1 L7
  midpoint L6 P17
  midpoint L10 P18
  midpoint P2 L12
  equal L7 L8
  dimension "d1539" diameter C1 = 4 (= "ptfe_od")
  dimension "d1551" angle L7 L12 = 45
  dimension "d1552" distance P9 P10 = 1 (= "ptfe_od / 4")
extrude "Extrude27" cut sketch "Sketch44" profile of C1 L6 L7 L8 L9 L10 L11 no distance stored
chamfer "Chamfer5" distance 0.6667 (= "wall_thickness / 3")
coil_primitive "CoilPrimitive1" Diameter 23.3333 (= "leadscrew_od + leadscrew_tooth_height") SectionSize 6.6667 (= "leadscrew_tooth_height * 2") TaperAngle 0 Pitch 30 (= "leadscrew_pitch") Revolutions 0.875 (= "leadscrew_turns / 2 - 1 / 8") bodies "groove"
mirror "Mirror1" mirrorStitchTolerance 0.1
loft "Loft1"
mirror "Mirror2" mirrorStitchTolerance 0.1
extrude "Extrude8" new body sketch "Sketch1" profile of C1 L1 L10 L12 L13 along normal blind 139.172 (= "leadscrew_length - ( leadscrew_center_position + bearing_z / 2 - stack_unit )") and against normal blind 60.828 (= "leadscrew_center_position + bearing_z / 2 - stack_unit") bodies "leadscrew"
combine "Combine7" bodies "groove"
revolve "Revolve1" sketch "Sketch1" AlongAngle 360 bodies "leadscrew_tooth"
extrude "Extrude14" new body sketch "Sketch1" profile of L6 L7 L9 L8 to an object Side2Offset 0 bodies "leadscrew_pin"
fillet "Fillet4" radius 4 (= "wall_thickness * 2")
chamfer "Chamfer3" distance 2 (= "wall_thickness")
move "Move8" RotateAngle 90
move "Move9" TranslateX 0 TranslateY 0 TranslateZ 7.5 (= "leadscrew_pitch / 4")
combine "Combine4"
move "Move6" RotateAngle 180
move "Move10" RotateAngle -128.954 (= "-2 * leadscrew_angle")
combine "Combine6"
sketch "tooth_trim" plane through (0, -24.6, 0) normal (0, 1, 0) x axis (-1, 0, 0)
  line L1 (0, 7.5) -> (4.5121, 9.6544)
  line L2 (-1.122, 9.8499) -> (0, 7.5)
  curve K1 (-1.122, 9.8499) -> (2.7142, 11.6992)
  curve K2 (4.9719, 6.9707) -> (4.5121, 9.6544)
  line L3 (0, 7.5) -> (4.5121, 9.6544)
  line L4 (1.122, 5.1501) -> (0, 7.5)
  curve K3 (4.9719, 6.9707) -> (1.122, 5.1501)
  curve K4 (4.9719, 6.9707) -> (4.5121, 9.6544)
  line L5 (0, 7.5) -> (4.5121, 9.6544)
  curve K5 (4.5121, 9.6544) -> (2.7142, 11.6992)
  line L6 (1.122, 5.1501) -> (0, 7.5)
  curve K6 (4.9719, 6.9707) -> (1.122, 5.1501)
  curve K7 (1.122, 5.1501) -> (-2.7142, 3.3008)
  line L7 (-1.122, 9.8499) -> (0, 7.5)
  curve K8 (-4.9719, 8.0293) -> (-1.122, 9.8499)
  curve K9 (-4.9719, 8.0293) -> (-4.5121, 5.3456)
  line L8 (0, 7.5) -> (-4.5121, 5.3456)
  curve K10 (2.7142, 11.6992) -> (-2.1544, 12.0121)
  curve K11 (4.5121, 9.6544) -> (2.7142, 11.6992)
  curve K12 (4.9719, 6.9707) -> (4.5121, 9.6544)
  curve K13 (2.1544, 2.9879) -> (4.9719, 6.9707)
  curve K14 (-2.7142, 3.3008) -> (2.1544, 2.9879)
  curve K15 (-4.5121, 5.3456) -> (-2.7142, 3.3008)
  curve K16 (-4.9719, 8.0293) -> (-4.5121, 5.3456)
  curve K17 (-2.1544, 12.0121) -> (-4.9719, 8.0293)
  circle C1 centre (0, 7.5) radius 5
extrude "Extrude10" sketch "tooth_trim" profile of C1 K1 K2 K3 K4 K6 K7 K8 K10 K12 K13 K14 K17 no distance stored
shell "Shell3" innerThickness 2 (= "wall_thickness")
copy_paste_bodies "CopyPasteBodies4"
align "Align4"
combine "Combine9" bodies "spur_gear_50t_7mm (1)"
sketch "lathe" plane through (0, 0, 0) normal (0, 1, 0) x axis (1, 0, 0)
  line L1 (30, 25) -> (0, -5)
  line L2 (0, 26.4142) -> (30.5858, 26.4142)
  line L3 (13, 44.8284) -> (30, 27.8284)
  line L4 (13, 56.4284) -> (13, 44.8284)
  line L5 (0, 25) -> (30, 25)
  line L6 (0, 120) -> (0, -120)
  line L7 (13, -44.8284) -> (30, -27.8284)
  line L8 (0, -44.8284) -> (13, -44.8284)
  line L9 (0, 44.8284) -> (13, 44.8284)
  line L10 (10, 63.4284) -> (10, 56.4284)
  line L11 (0, 63.4284) -> (10, 63.4284)
  line L12 (0, -26.4142) -> (30.5858, -26.4142)
  line L13 (0, 56.4284) -> (13, 56.4284)
  line L14 (13, 63.4284) -> (10, 63.4284)
  line L15 (13, 75.0284) -> (13, 63.4284)
  line L16 (0, 75.0284) -> (13, 75.0284)
  line L17 (0, 59.9284) -> (10, 59.9284)
  line L18 (13, 86.6284) -> (13, 75.0284)
  line L19 (0, 86.6284) -> (13, 86.6284)
  line L20 (240, 120) -> (0, 120)
  line L21 (240, -120) -> (240, 120)
  line L22 (0, -120) -> (240, -120)
  line L23 (5, 0) -> (30, -25)
  line L24 (0, -5) -> (5, 0)
  line L25 (0, -25) -> (30, -25)
  line L26 (0, 0) -> (5, 0)
  line L27 (25, -20) -> (25, 20)
  line L28 (175, 120) -> (10.1716, -44.8284)
  line L29 (3.5858, -1.4142) -> (28.5858, -26.4142)
  line L30 (0, -113.3716) -> (10, -113.3716)
  line L31 (10, -52.0711) -> (10, -113.3716)
  line L32 (7.8377, -111.3716) -> (7.8377, -52.0711)
  line L33 (28.5858, 26.4142) -> (0, -2.1716)
  line L34 (10.1716, 44.8284) -> (28.5858, 26.4142)
  line L35 (10, 67.7858) -> (10, 52.0711)
  line L36 (7.8377, 52.0711) -> (7.8377, 67.7858)
  line L37 (10.8377, 86.6284) -> (10.8377, 79.0501)
  line L38 (0, 22) -> (27, 22)
  line L39 (27, -40) -> (27, 22)
  line L40 (0, -111.3716) -> (7.8377, -111.3716)
  line L41 (0, 84.6284) -> (10.8377, 84.6284)
  line L42 (10, -116.0292) -> (10, -113.3716)
  arc A1 centre (28.5858, -26.4142) radius 2 clockwise from (30, -25) to (30, -27.8284)
  arc A2 centre (28.5858, 26.4142) radius 2 clockwise from (30, 27.8284) to (30, 25)
  arc A3 centre (20.2426, -52.0711) radius 10.2426 clockwise from (10, -52.0711) to (13, -44.8284)
  arc A4 centre (20.2426, -52.0711) radius 12.4049 clockwise from (7.8377, -52.0711) to (10.1716, -44.8284)
  arc A5 centre (20.2426, 52.0711) radius 10.2426 clockwise from (13, 44.8284) to (10, 52.0711)
  arc A6 centre (20.2426, 52.0711) radius 12.4049 clockwise from (10.1716, 44.8284) to (7.8377, 52.0711)
  arc A7 centre (20.2426, 67.7858) radius 12.4049 clockwise from (7.8377, 67.7858) to (9.4809, 73.9557)
  arc A8 centre (0.5951, 79.0501) radius 10.2426 clockwise from (10.8377, 79.0501) to (9.4809, 73.9557)
  arc A9 centre (0.5951, 79.0501) radius 12.4049 clockwise from (13, 79.0501) to (11.3568, 72.8802)
  arc A10 centre (20.2426, 67.7858) radius 10.2426 clockwise from (10, 67.7858) to (11.3568, 72.8802)
  point P6 (30, 25)
  point P1 (0, 0)
  point P2 (0, 26.4142)
  point P7 (0, 25)
  point P12 (0, -44.8284)
  point P13 (0, 44.8284)
  point P16 (0, 63.4284)
  point P17 (0, -26.4142)
  point P18 (0, 56.4284)
  point P14 (10, 56.4284)
  point P21 (0, 75.0284)
  point P22 (10, 59.9284)
  point P23 (0, 59.9284)
  point P24 (28.5858, -26.4142)
  point P25 (30, -27.8284)
  point P30 (30, -27.8284)
  point P32 (30.5858, 26.4142)
  point P10 (30.5858, -26.4142)
  point P3 (30, 27.8284)
  point P29 (30, 27.8284)
  point P28 (30, 25)
  point P31 (30, 25)
  point P35 (0, 86.6284)
  point P27 (28.5858, 26.4142)
  point P40 (0, -5)
  point P41 (30, -25)
  point P42 (0, -25)
  point P36 (0, -5)
  point P44 (0, 0)
  point P45 (25, 20)
  point P46 (25, -20)
  point P47 (10.1716, -44.8284)
  point P48 (175, 120)
  point P20 (13, 75.0284)
  point P33 (13, 75.0284)
  point P49 (28.5858, -26.4142)
  point P50 (3.5858, -1.4142)
  point P52 (0, -113.3716)
  point P53 (10, -52.0711)
  point P55 (10, -52.0711)
  point P54 (20.2426, -52.0711)
  point P56 (20.2426, -52.0711)
  point P37 (5, 0)
  point P43 (5, 0)
  point P59 (0, -2.1716)
  point P60 (28.5858, 26.4142)
  point P61 (28.5858, 26.4142)
  point P62 (10.1716, 44.8284)
  point P63 (20.2426, 52.0711)
  point P66 (20.2426, 52.0711)
  point P73 (10.8377, 86.6284)
  point P71 (0.5951, 79.0501)
  point P74 (0.5951, 79.0501)
  point P75 (11.3568, 72.8802)
  point P78 (11.3568, 72.8802)
  point P76 (13, 79.0501)
  point P68 (20.2426, 67.7858)
  point P77 (20.2426, 67.7858)
  point P79 (27, 22)
  point P80 (0, 22)
  point P82 (27, -9)
  point P84 (0, -111.3716)
  point P85 (10.8377, 84.6284)
  point P86 (0, 84.6284)
  point P58 (7.8377, -111.3716)
  point P83 (7.8377, -111.3716)
  point P51 (10, -113.3716)
  point P87 (10, -113.3716)
  point P8 (0, -120)
  point P9 (0, 120)
  point P5 (13, 44.8284)
  point P4 (13, 56.4284)
  point P19 (13, 63.4284)
  point P15 (10, 63.4284)
  point P34 (13, 86.6284)
  point P81 (27, -40)
  coincident L1 P6
  vertical L6
  midpoint P1 L6
  perpendicular L2 L6
  coincident P2 L6
  coincident P7 L6
  perpendicular L5 L6
  coincident L6 P12
  perpendicular L6 L8
  coincident L6 P13
  perpendicular L6 L9
  equal L3 L7
  coincident L6 P16
  perpendicular L6 L11
  coincident L6 P17
  perpendicular L6 L12
  equal L2 L12
  equal L8 L9
  coincident L6 P18
  perpendicular L6 L13
  coincident P14 L13
  perpendicular L10 L14
  coincident L6 P21
  perpendicular L6 L16
  perpendicular L15 L16
  perpendicular L4 L13
  midpoint L10 P22
  coincident L6 P23
  perpendicular L6 L17
  coincident L12 P24
  coincident P25 P30
  midpoint A2 P32
  midpoint P10 A1
  coincident P3 P29
  coincident P28 P31
  tangent L3 A2
  coincident L6 P35
  perpendicular L6 L19
  perpendicular L18 L19
  coincident L2 P27
  equal A1 A2
  perpendicular L6 L20
  perpendicular L20 L21
  perpendicular L6 L22
  equal L6 L20
  tangent A1 L23
  coincident L6 P40
  parallel L7 L24
  parallel L3 L23
  coincident L23 P41
  coincident L6 P42
  perpendicular L6 L25
  equal L5 L25
  coincident L6 P36
  coincident P1 P44
  perpendicular L6 L26
  coincident L1 P45
  coincident L23 P46
  vertical L27
  coincident L8 P47
  parallel L7 L28
  coincident L20 P48
  coincident P20 P33
  coincident P24 P49
  coincident L24 P50
  perpendicular L24 L29
  coincident L6 P52
  perpendicular L6 L30
  perpendicular L30 L31
  coincident P53 P55
  tangent L31 A3
  tangent L7 A3
  coincident P54 P56
  perpendicular L30 L32
  tangent A4 L32
  coincident P37 P43
  coincident L1 P37
  coincident L6 P59
  coincident P27 P60
  coincident P27 P61
  coincident L9 P62
  parallel L3 L34
  parallel L1 L33
  tangent A5 L35
  tangent L3 A5
  parallel L6 L35
  collinear L10 L35
  coincident P63 P66
  equal A6 A7
  tangent A7 L36
  tangent A6 L36
  tangent A7 A8
  coincident L19 P73
  perpendicular L19 L37
  tangent A8 L37
  coincident P71 P74
  tangent L10 A10
  coincident P75 P78
  coincident L18 P76
  tangent A9 A10
  tangent L18 A9
  tangent L35 A10
  parallel L35 L36
  coincident P68 P77
  midpoint P22 L35
  equal A8 A10
  coincident L1 P79
  coincident L6 P80
  perpendicular L6 L38
  perpendicular L38 L39
  midpoint L39 P82
  coincident L6 P84
  perpendicular L6 L40
  coincident L37 P85
  coincident L6 P86
  perpendicular L6 L41
  perpendicular L30 L42
  coincident P58 P83
  coincident P51 P87
  dimension "d597_1" distance P6 P7 = 30 (= "spool_id_max / 2")
  dimension "d604_1" distance P8 P9 = 240 (= "buildplate_limit")
  dimension "d605_1" angle L2 L3 = 45 (= "overhang_angle")
  dimension "d606_1" angle L1 L2 = 45 (= "overhang_angle")
  dimension "d610_1" distance P5 P13 = 13 (= "axle_od / 2")
  dimension "d619_1" distance L6 L10 = 10 (= "spur_gear_diameter_small / 2")
  dimension "d621_1" distance P4 P5 = 11.6 (= "stack_unit")
  dimension "d622_1" distance P19 P20 = 11.6 (= "stack_unit")
  dimension "d624_1" distance L6 L15 = 13 (= "axle_od / 2")
  dimension "d625_1" distance P14 P15 = 7 (= "bearing_z")
  dimension "d654_1" distance L6 P28 = 30 (= "spool_id_max / 2")
  dimension "d693_1" distance P33 P34 = 11.6 (= "stack_unit")
  dimension "d847" radius A2 = 2 (= "fillet_radius")
  dimension "d857" distance L5 L25 = 50 (= "spool_z_min")
  dimension "d876" distance L6 L27 = 25 (= "spool_id_min / 2")
  dimension "d885" distance L7 L28 = 2 (= "wall_thickness")
  dimension "d1708" distance L19 L30 = 200
  dimension "d1709" distance L6 L31 = 10 (= "spur_gear_diameter_small / 2")
  dimension "d1724" distance L17 P45 = 39.9284
  dimension "d1725" distance L6 L39 = 27 (= "spool_id_bambu / 2")
  dimension "d1726" distance P79 P81 = 62 (= "spool_interface_z_bambu")
  dimension "d1728" distance L17 P82 = 68.9284
  dimension "d1729" distance L30 L40 = 2 (= "wall_thickness")
  dimension "d1730" distance L19 L41 = 2 (= "wall_thickness")
sketch "screw" plane through (0, 0, 0) normal (0, 0, 1) x axis (1, 0, 0)
  line L1 (0, -16.625) -> (0, 16.625)
  circle C1 centre (0, 0) radius 16.625
  circle C2 centre (0, 0) radius 14.625
  circle C3 centre (0, 1.625) radius 13
  circle C4 centre (0, 0) radius 11.375
  circle C5 centre (0, 1.625) radius 12.7
  circle C6 centre (0, 1.625) radius 15
  circle C7 centre (0, 1.625) radius 10.7
  point P1 (0, 0)
  point P2 (0, 0)
  point P5 (0, 16.625)
  point P6 (0, -16.625)
  point P4 (0, 1.625)
  point P3 (0, 0)
  point P8 (0, -11.375)
  point P9 (0, 14.625)
  coincident P1 P2
  concentric C1 C2
  coincident C1 P5
  coincident C1 P6
  vertical L1
  coincident P4 L1
  coincident P3 L1
  concentric C1 C4
  coincident L1 P8
  coincident C3 P8
  coincident C4 P8
  coincident L1 P9
  coincident C2 P9
  coincident C3 P9
  concentric C3 C7
  dimension "d878" distance C1 C2 = 2 (= "wall_thickness")
  dimension "d879" distance C2 C4 = 3.25 (= "axle_od / 8")
  dimension "d880" = 2 (= "wall_thickness")
  dimension "d1710" diameter C3 = 26 (= "axle_od")
  dimension "d1711" diameter C1 = 33.25
  dimension "d1712" distance C5 C7 = 2 (= "wall_thickness")
sweep "Sweep2" sketch "screw" TwistAngle 3323.077 (= "( buildplate_limit / axle_od ) * 360 deg") named "d442_1" TaperAngle 0 named "d443_1" bodies "spool_active_bolt"
sweep "Sweep6" sketch "screw" TwistAngle 3323.077 (= "( buildplate_limit / axle_od ) * 360 deg") TaperAngle 0 bodies "nut_negative"
sweep "Sweep7" sketch "screw" TwistAngle 3323.077 (= "( buildplate_limit / axle_od ) * 360 deg") TaperAngle 0 bodies "nut_positive"
sweep "Sweep8" sketch "screw" TwistAngle 3323.077 (= "( 360 * ( buildplate_limit / axle_od ) ) * 1 deg") TaperAngle 0
revolve "Revolve6" sketch "lathe" AlongAngle 360 bodies "spindle_female"
remove_body "RemoveBody35"
revolve "Revolve10" sketch "lathe" AlongAngle 360
revolve "Revolve9" sketch "lathe" AlongAngle 360
combine "Combine28" bodies "nut_negative"
revolve "Revolve11" sketch "lathe" AlongAngle 360
fillet "Fillet6" radius 2 (= "fillet_radius")
copy_paste_bodies "CopyPasteBodies12"
move "Move5" TranslateX 0 TranslateY 0 TranslateZ 40
revolve "Revolve15" sketch "lathe" AlongAngle 360
revolve "Revolve7" sketch "lathe" AlongAngle 360 bodies "spindle_male_driven"
remove_body "RemoveBody40"
revolve "Revolve8" sketch "lathe" AlongAngle 360 bodies "spool_cap"
revolve "Revolve12" sketch "lathe" AlongAngle 360
combine "Combine30"
copy_paste_bodies "CopyPasteBodies11"
revolve "Revolve14" sketch "lathe" AlongAngle 360
chamfer "Chamfer5" distance 2 (= "wall_thickness")
copy_paste_bodies "CopyPasteBodies10"
align "Align7"
move "Move3" RotateAngle 90
move "Move4" TranslateX 0 TranslateY 0 TranslateZ -3.5 (= "-bearing_z / 2")
sketch "Sketch13" plane through (0, 0, -44.8284) normal (0, 0, -1) x axis (-1, 0, 0)
  circle C1 centre (0, 0) radius 13
  circle C2 centre (0, 0) radius 13
  circle C3 centre (0, 0) radius 10.1716
  circle C4 centre (0, 0) radius 10.1716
